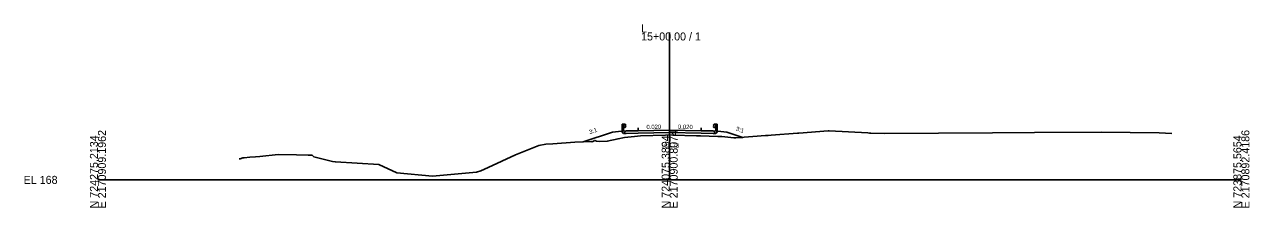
# Model space of a CAD drawing. Extents: x -26 to 2803, y -10 to 9553.
# Drawn here: x -25.7 to 402.8, y 5990.3 to 6054.4 of the extents above; entities that cross this region are included whole.
import ezdxf

# ---------------------------------------------------------------- set-up
doc = ezdxf.new("R2010")
doc.units = 0
for name, color, linetype in [('Exist Cross Section Cell', 7, 'Continuous'), ('Exist XS Center Line Elevation Label', 7, 'Continuous'), ('Exist XS Ground Line', 7, 'Continuous'), ('Prop XS Dump Level', 7, 'Continuous'), ('Prop XS Earthwork Shape', 7, 'Continuous'), ('Prop XS EOT Tick Mark', 7, 'Continuous'), ('Prop XS Finish Grade', 7, 'Continuous'), ('Prop XS Finish Grade Earthwork', 7, 'Continuous'), ('Prop XS Finish Grade Paved Shoulder', 7, 'Continuous'), ('Prop XS Finish Grade Pavement', 7, 'Continuous'), ('Prop XS Guardrail', 7, 'Continuous'), ('Prop XS Pvmt Edge Slope', 7, 'Continuous'), ('Prop XS SE Text', 7, 'Continuous'), ('Prop XS Side Slope Text', 7, 'Continuous'), ('Prop XS Subgrade Earthwork', 7, 'Continuous')]:
    doc.layers.add(name, color=color, linetype=linetype)

msp = doc.modelspace()

# ---------------------------------------------------------------- linework, layer by layer
at = {"layer": 'Exist Cross Section Cell'}
for p, q in [((200, 6000), (200, 6051.65)), ((0, 6000), (200, 6000)), ((200, 6000), (400, 6000))]:
    msp.add_line(p, q, dxfattribs=at)
at = {"layer": 'Exist XS Ground Line'}
msp.add_lwpolyline([(49.43, 6007.39), (49.75, 6007.38), (50.68, 6007.76), (51.13, 6007.76), (53.08, 6007.95), (55.11, 6008.05), (56.68, 6008.22), (62.99, 6008.9), (69.41, 6008.73), (73.52, 6008.6), (74.93, 6008.6), (75.54, 6008.06), (82.06, 6006.48), (83.05, 6006.31), (98.25, 6005.35), (104.5, 6002.51), (117.05, 6001.32), (132.4, 6002.75), (133.89, 6003.19), (136.46, 6004.34), (146.03, 6008.77), (154.19, 6012.02), (156.73, 6012.51), (159.08, 6012.66), (166.8, 6013.2), (172.59, 6013.47), (172.88, 6013.34), (173.85, 6013.81), (174.39, 6013.57), (175.31, 6013.49), (178.17, 6013.51), (181.93, 6014.43), (184.24, 6014.88), (187.7, 6015.24), (189.84, 6015.41), (198.49, 6015.7), (199.85, 6015.74), (201.14, 6015.69), (209.41, 6015.43), (210.78, 6015.42), (216.83, 6015.24), (218.2, 6015.2), (222.39, 6014.69), (223.1, 6014.69), (233.58, 6015.59), (234.41, 6015.6), (235.51, 6015.68), (244.75, 6016.36), (245.19, 6016.42), (255.43, 6017.16), (255.82, 6017.22), (269.27, 6016.44), (269.91, 6016.38), (270.38, 6016.34), (275.13, 6016.3), (312.88, 6016.5), (327.66, 6016.55), (350.95, 6016.72), (371.25, 6016.5), (375.65, 6016.19)], dxfattribs=at)
at = {"layer": 'Prop XS Dump Level'}
for p, q in [((189, 6017.22), (200, 6017.44)), ((200, 6017.44), (211, 6017.22))]:
    msp.add_line(p, q, dxfattribs=at)
at = {"layer": 'Prop XS Earthwork Shape'}
msp.add_lwpolyline([(216.1, 6016.28), (216.82, 6017.01), (220, 6016.75), (225.56, 6014.9), (223.1, 6014.69), (222.39, 6014.69), (218.2, 6015.2), (216.83, 6015.24), (210.78, 6015.42), (209.41, 6015.43), (201.14, 6015.69), (199.85, 6015.74), (198.49, 6015.7), (189.84, 6015.41), (187.7, 6015.24), (184.24, 6014.88), (181.93, 6014.43), (178.17, 6013.51), (175.31, 6013.49), (174.39, 6013.57), (173.85, 6013.81), (172.88, 6013.34), (172.59, 6013.47), (169.76, 6013.34), (180, 6016.75), (183.18, 6017.01), (183.9, 6016.28), (184.75, 6016.3), (189, 6016.38), (200, 6016.6), (211, 6016.38), (215.25, 6016.3)], close=True, dxfattribs=at)
at = {"layer": 'Prop XS EOT Tick Mark'}
for p, q in [((189, 6017.22), (189, 6018.22)), ((211, 6017.22), (211, 6018.22))]:
    msp.add_line(p, q, dxfattribs=at)
at = {"layer": 'Prop XS Finish Grade'}
for p, q in [((184.75, 6017.13), (183.18, 6017.01)), ((215.25, 6017.13), (216.82, 6017.01))]:
    msp.add_line(p, q, dxfattribs=at)
at = {"layer": 'Prop XS Finish Grade Earthwork'}
for p, q in [((180, 6016.75), (169.76, 6013.34)), ((183.18, 6017.01), (180, 6016.75)), ((216.82, 6017.01), (220, 6016.75)), ((220, 6016.75), (225.56, 6014.9))]:
    msp.add_line(p, q, dxfattribs=at)
at = {"layer": 'Prop XS Finish Grade Paved Shoulder'}
for p, q in [((189, 6017.22), (184.75, 6017.13)), ((211, 6017.22), (215.25, 6017.13))]:
    msp.add_line(p, q, dxfattribs=at)
at = {"layer": 'Prop XS Finish Grade Pavement'}
for p, q in [((189, 6017.22), (200, 6017.44)), ((200, 6017.44), (211, 6017.22))]:
    msp.add_line(p, q, dxfattribs=at)
at = {"layer": 'Prop XS Guardrail'}
for p, q in [((183.34, 6019.47), (183.84, 6019.47)), ((183.34, 6016.97), (183.34, 6019.47)), ((183.84, 6019.47), (184.34, 6019.47)), ((183.84, 6019.47), (183.84, 6016.97)), ((184.34, 6018.34), (183.84, 6018.34)), ((184.34, 6019.47), (184.63, 6019.27)), ((184.63, 6019.15), (184.34, 6018.95)), ((184.34, 6018.95), (184.34, 6018.86)), ((184.34, 6018.86), (184.63, 6018.66)), ((184.63, 6018.54), (184.34, 6018.34)), ((184.63, 6019.27), (184.66, 6019.21)), ((184.66, 6019.21), (184.63, 6019.15)), ((184.63, 6018.66), (184.66, 6018.6)), ((184.66, 6018.6), (184.63, 6018.54)), ((215.33, 6019.26), (215.3, 6019.2)), ((215.3, 6019.2), (215.33, 6019.14)), ((215.33, 6018.64), (215.3, 6018.58)), ((215.3, 6018.58), (215.33, 6018.52)), ((215.62, 6019.46), (215.33, 6019.26)), ((215.33, 6019.14), (215.62, 6018.94)), ((215.62, 6018.84), (215.33, 6018.64)), ((215.33, 6018.52), (215.62, 6018.32)), ((216.12, 6019.46), (215.62, 6019.46)), ((215.62, 6018.94), (215.62, 6018.84)), ((215.62, 6018.32), (216.12, 6018.32)), ((216.62, 6019.46), (216.12, 6019.46)), ((216.12, 6019.46), (216.12, 6016.96)), ((216.62, 6016.96), (216.62, 6019.46))]:
    msp.add_line(p, q, dxfattribs=at)
at = {"layer": 'Prop XS Pvmt Edge Slope'}
for p, q in [((184.75, 6017.13), (183.9, 6016.28)), ((215.25, 6017.13), (216.1, 6016.28))]:
    msp.add_line(p, q, dxfattribs=at)
at = {"layer": 'Prop XS Subgrade Earthwork'}
for p, q in [((183.9, 6016.28), (183.18, 6017.01)), ((200, 6016.6), (189, 6016.38)), ((211, 6016.38), (200, 6016.6)), ((216.1, 6016.28), (216.82, 6017.01)), ((184.75, 6016.3), (183.9, 6016.28)), ((189, 6016.38), (184.75, 6016.3)), ((211, 6016.38), (215.25, 6016.3)), ((215.25, 6016.3), (216.1, 6016.28))]:
    msp.add_line(p, q, dxfattribs=at)

# ---------------------------------------------------------------- texts
at = {"layer": 'Exist Cross Section Cell'}
for s, p in [('15+00.00 / 1', (190, 6048.85)), ('L', (190, 6051.65)), ('EL 168', (-26, 5998.6))]:
    msp.add_text(s, height=2.8, dxfattribs=at).set_placement(p)
for s, p in [('E 2170909.1962', (2.8, 5990)), ('E 2170900.8074', (202.8, 5990)), ('E 2170892.4186', (402.8, 5990)), ('N 724275.2134', (0, 5990)), ('N 724075.3894', (200, 5990)), ('N 723875.5654', (400, 5990))]:
    msp.add_text(s, height=2.8, rotation=90, dxfattribs=at).set_placement(p)
at = {"layer": 'Exist XS Center Line Elevation Label'}
msp.add_text('183.73', height=1.5, dxfattribs=at).set_placement((196.99, 6011.23))
at = {"layer": 'Prop XS Dump Level'}
msp.add_text('Case2', height=0.04, dxfattribs=at).set_placement((216.18, 6016.95))
at = {"layer": 'Prop XS SE Text'}
for rotation, p in [(1.1458, (191.88, 6017.77)), (358.8542, (202.88, 6017.88))]:
    msp.add_text('0.020', height=1.5, rotation=rotation, dxfattribs=at).set_placement(p)
at = {"layer": 'Prop XS Side Slope Text'}
for rotation, p in [(18.4349, (172.07, 6015.98)), (341.5651, (223.02, 6017.31))]:
    msp.add_text('3:1', height=1.5, rotation=rotation, dxfattribs=at).set_placement(p)

doc.saveas('drawing.dxf')
